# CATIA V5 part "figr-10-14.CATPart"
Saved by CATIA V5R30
Part number: Part1
Bounding box of the stored display mesh (mm): x 0 to 0, y 0 to 59.085, z 0 to 150
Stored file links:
  D:\PROJECTS\CATIA V56R 2020\Resources\Parts File\c10_catia_v5_6r2020_prt\figr-10-14.CATPart
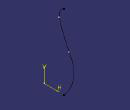
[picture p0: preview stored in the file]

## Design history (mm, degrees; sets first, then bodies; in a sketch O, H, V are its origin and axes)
Set1
  Sketch1 on yz-plane, origin (0, 0, 0), H (0, 1, 0), V (0, 0, 1)
    arc A1 centre (219.5293, 176.8574) radius 194.8379 from (50.3627, 80.1907) to (30.3627, 130.1907) cw
    arc A2 centre (-7.8186, 46.9443) radius 67.0103 from (50.3627, 80.1907) to (40, 0) cw
    arc A3 centre (47.0688, 134.312) radius 17.207 from (30.3627, 130.1907) to (40, 150) cw
    axis line L1 (0, 156.5671) -> (0, -24.1442)
    vertical: L1 V
  Revol1: Element1 Sketch1, Angle1 -60
Body1 (main body)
